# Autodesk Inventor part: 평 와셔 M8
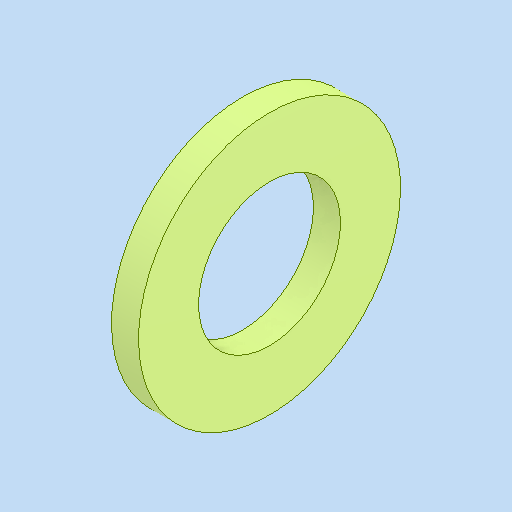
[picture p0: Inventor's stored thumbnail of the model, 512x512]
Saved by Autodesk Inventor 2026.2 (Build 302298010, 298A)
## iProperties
Created: 2026-08
Part Number: 평 와셔 M8
Material: 강철, 연강
Description: 평면 와셔
Document SubType Name: Modeling
Designer: PC-2-06
Density: 7.85 g/cm^3
Appearance: 기본값
Author: jhkim
Sending System: Autodesk Inventor 2027
Preprocessor: ST-DEVELOPER v20.1
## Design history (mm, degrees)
feature "Solid1"
node "솔리드1"
